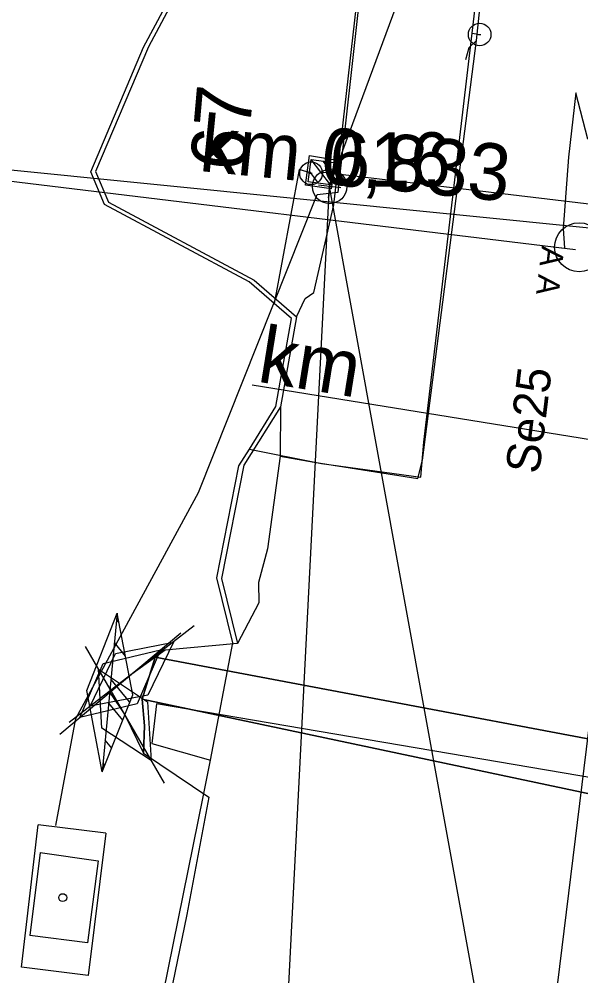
# Model space of a CAD drawing. Extents: x -598638 to -597933, y -1164002 to -1161904.
# Drawn here: x -598553.48 to -598528.63, y -1163497.55 to -1163455.25 of the extents above; entities that cross this region are included whole.
import ezdxf

# ---------------------------------------------------------------- set-up
doc = ezdxf.new("R2010")
doc.units = 0
for name, color, linetype in [('Vrstva 1', 7, 'Continuous'), ('Vrstva 11', 7, 'Continuous'), ('Vrstva 12', 7, 'Continuous'), ('Vrstva 16', 7, 'Continuous'), ('Vrstva 23', 7, 'Continuous'), ('Vrstva 25', 7, 'Continuous'), ('Vrstva 26', 7, 'Continuous'), ('Vrstva 28', 7, 'Continuous'), ('Vrstva 3', 7, 'Continuous'), ('Vrstva 31', 7, 'Continuous'), ('Vrstva 35', 7, 'Continuous'), ('Vrstva 51', 7, 'Continuous'), ('Vrstva 59', 7, 'Continuous'), ('Vrstva 6', 7, 'Continuous'), ('Vrstva 63', 7, 'Continuous'), ('Vrstva 7', 7, 'Continuous')]:
    doc.layers.add(name, color=color, linetype=linetype)

msp = doc.modelspace()

# ---------------------------------------------------------------- linework, layer by layer
at = {"layer": 'Vrstva 1'}
msp.add_line((-598564.645, -1163460.828), (-598504.943, -1163466.8), dxfattribs=at)
at = {"layer": 'Vrstva 11'}
for p, q in [((-598539.706, -1163462.573), (-598540.557, -1163461.449)), ((-598539.631, -1163462.052), (-598540.035, -1163461.518)), ((-598540.231, -1163462.501), (-598540.63, -1163461.974))]:
    msp.add_line(p, q, dxfattribs=at)
msp.add_lwpolyline([(-598540.694, -1163462.437), (-598540.557, -1163461.446), (-598539.566, -1163461.583), (-598539.703, -1163462.574)], close=True, dxfattribs=at)
for points in [[(-598540.694, -1163462.437), (-598540.557, -1163461.446), (-598539.566, -1163461.583), (-598539.703, -1163462.574), (-598540.694, -1163462.437)], [(-598518.75, -1163464.56), (-598540.13, -1163462.01)]]:
    msp.add_lwpolyline(points, dxfattribs=at)
at = {"layer": 'Vrstva 12'}
msp.add_lwpolyline([(-598539.48, -1163461.47), (-598539.67, -1163462.75), (-598540.81, -1163462.58), (-598540.63, -1163461.28), (-598539.48, -1163461.47)], dxfattribs=at)
at = {"layer": 'Vrstva 16'}
for points in [[(-598549.644, -1163491.237), (-598550.426, -1163497.528), (-598553.376, -1163497.172), (-598552.644, -1163490.864)], [(-598549.644, -1163491.237), (-598552.644, -1163490.864)]]:
    msp.add_lwpolyline(points, dxfattribs=at)
at = {"layer": 'Vrstva 23'}
for points in [[(-598552.552, -1163492.091), (-598549.985, -1163492.468), (-598550.449, -1163496.09), (-598553.014, -1163495.766)], [(-598552.552, -1163492.091), (-598553.014, -1163495.766)]]:
    msp.add_lwpolyline(points, dxfattribs=at)
at = {"layer": 'Vrstva 25'}
for p, q in [((-598533.157, -1163455.923), (-598533.057, -1163455.923)), ((-598540.616, -1163462.062), (-598540.516, -1163462.062))]:
    msp.add_line(p, q, dxfattribs=at)
for centre in [(-598533.107, -1163455.923), (-598540.566, -1163462.062)]:
    msp.add_circle(centre, 0.5, dxfattribs=at)
at = {"layer": 'Vrstva 26'}
for points in [[(-598545.332, -1163489.631), (-598545.008, -1163488.013), (-598544.032, -1163482.82), (-598544.736, -1163479.954), (-598543.755, -1163474.998), (-598543.294, -1163474.254), (-598542.12, -1163472.372), (-598541.435, -1163468.483), (-598542.191, -1163467.82), (-598543.3, -1163466.865), (-598549.702, -1163463.438), (-598550.312, -1163461.998), (-598547.972, -1163456.485), (-598545.109, -1163451.121), (-598540.175, -1163430.965), (-598539.287, -1163425.257), (-598536.381, -1163402.898), (-598536.647, -1163397.91), (-598537.412, -1163388.462)], [(-598543.294, -1163474.254), (-598540.098, -1163474.897), (-598535.703, -1163475.505), (-598535.584, -1163473.956), (-598533.441, -1163455.87), (-598532.804, -1163450.473), (-598532.749, -1163449.438), (-598531.188, -1163437.14), (-598531.046, -1163436.005), (-598530.738, -1163436.041)], [(-598551.86, -1163490.896), (-598550.979, -1163486.167), (-598545.539, -1163476.175), (-598540.296, -1163462.996), (-598539.364, -1163462.898), (-598538.397, -1163454.139), (-598537.686, -1163454.273)], [(-598533.441, -1163455.87), (-598533.107, -1163455.923)], [(-598540.566, -1163462.062), (-598541.095, -1163461.89), (-598542.191, -1163467.82)], [(-598515.761, -1163490.906), (-598547.407, -1163485.525), (-598547.611, -1163487.268), (-598545.008, -1163488.013)], [(-598588.761, -1163677.265), (-598581.48, -1163677.548), (-598580.673, -1163676.998), (-598579.793, -1163670.74), (-598579.104, -1163665.83), (-598575.81, -1163633.898), (-598573.543, -1163615.779), (-598569.61, -1163583.767), (-598565.804, -1163555.196), (-598563.346, -1163534.245), (-598552.733, -1163534.833), (-598552.296, -1163533.988), (-598551.287, -1163526.393), (-598548.728, -1163507.111), (-598547.312, -1163499.378), (-598545.332, -1163489.631)]]:
    msp.add_lwpolyline(points, dxfattribs=at)
at = {"layer": 'Vrstva 28'}
for p, q in [((-598545.735, -1163482.079), (-598551.265, -1163486.341)), ((-598546.332, -1163482.39), (-598551.687, -1163486.87)), ((-598550.557, -1163482.987), (-598547.064, -1163489.032)), ((-598549.211, -1163483.288), (-598546.657, -1163482.79)), ((-598546.657, -1163482.79), (-598547.79, -1163485.132)), ((-598550.343, -1163485.63), (-598549.211, -1163483.288)), ((-598549.757, -1163483.737), (-598547.225, -1163483.137)), ((-598547.225, -1163483.137), (-598548.263, -1163485.523)), ((-598550.795, -1163486.123), (-598549.757, -1163483.737)), ((-598549.975, -1163483.995), (-598547.803, -1163485.427)), ((-598549.818, -1163486.592), (-598549.975, -1163483.995)), ((-598547.79, -1163485.132), (-598550.343, -1163485.63)), ((-598548.263, -1163485.523), (-598550.795, -1163486.123)), ((-598547.803, -1163485.427), (-598547.646, -1163488.024)), ((-598547.646, -1163488.024), (-598549.818, -1163486.592))]:
    msp.add_line(p, q, dxfattribs=at)
for points in [[(-598536.213, -1163400.645), (-598536.168, -1163402.882), (-598539.241, -1163426.522), (-598539.962, -1163430.949), (-598541.59, -1163438.158), (-598542.388, -1163441.691), (-598544.896, -1163451.105), (-598547.759, -1163456.469), (-598550.099, -1163461.982), (-598549.524, -1163463.34), (-598543.087, -1163466.786), (-598541.213, -1163468.412), (-598540.83, -1163467.6), (-598540.45, -1163467.34), (-598539.56, -1163463.45), (-598538.42, -1163453.46), (-598538.38, -1163452.75)], [(-598541.213, -1163468.412), (-598541.912, -1163472.382), (-598541.94, -1163474.57), (-598540.43, -1163474.83), (-598535.85, -1163475.55), (-598535.63, -1163474.75), (-598533.25, -1163456.19), (-598532.5, -1163449.06), (-598531.21, -1163437.8), (-598530.49, -1163437.59), (-598530.54, -1163438.36)], [(-598533.25, -1163456.19), (-598533.58, -1163456.51), (-598533.73, -1163457.04)], [(-598514.51, -1163484.35), (-598514.38, -1163480.67), (-598513.13, -1163475.45), (-598512.19, -1163471.82), (-598512.11, -1163471.2), (-598510.35, -1163465.26), (-598510.39, -1163463.95), (-598514.7, -1163462.74), (-598516.79, -1163462.2), (-598518.93, -1163461.77), (-598523.46, -1163461.36), (-598524.57, -1163461.22), (-598525.3, -1163460.94), (-598528.32, -1163460.55), (-598528.85, -1163458.5), (-598529.18, -1163461.35), (-598529.41, -1163464.51), (-598529.36, -1163465.37)], [(-598541.912, -1163472.382), (-598543.54, -1163474.971), (-598544.53, -1163479.976), (-598543.818, -1163482.855)], [(-598541.94, -1163474.57), (-598542.5, -1163478.67), (-598542.89, -1163480.16), (-598542.87, -1163481.06), (-598543.818, -1163482.855), (-598547.027, -1163483.149), (-598548.5, -1163484.21), (-598549.01, -1163484.63), (-598549.47, -1163485.021), (-598548.81, -1163486.01), (-598547.976, -1163487.695), (-598545.092, -1163489.642)], [(-598547.976, -1163487.695), (-598547.93, -1163486.49), (-598548.04, -1163485.31), (-598547.46, -1163483.46), (-598517.45, -1163489.12), (-598516.135, -1163489.246)], [(-598548.04, -1163485.31), (-598518.01, -1163491.67), (-598516.85, -1163491.33)], [(-598545.092, -1163489.642), (-598546.067, -1163494.842), (-598548.252, -1163505.51), (-598549.637, -1163514.935), (-598550.222, -1163519.898), (-598550.57, -1163526.69), (-598552.088, -1163534.212), (-598552.387, -1163534.867), (-598558.986, -1163534.224), (-598563.192, -1163534.27), (-598563.517, -1163536.001), (-598564.063, -1163540.493), (-598564.734, -1163547.322), (-598565.317, -1163553.309), (-598566.354, -1163561.262)]]:
    msp.add_lwpolyline(points, dxfattribs=at)
at = {"layer": 'Vrstva 3'}
msp.add_circle((-598528.707, -1163465.333), 1.084, dxfattribs=at)
at = {"layer": 'Vrstva 31'}
for p, q in [((-598549.065, -1163481.918), (-598549.164, -1163481.801)), ((-598548.768, -1163483.407), (-598549.26, -1163482.814)), ((-598548.597, -1163485.431), (-598549.415, -1163484.441)), ((-598548.893, -1163486.243), (-598549.515, -1163485.491)), ((-598549.376, -1163487.475), (-598549.669, -1163487.121)), ((-598549.704, -1163488.247), (-598549.766, -1163488.134))]:
    msp.add_line(p, q, dxfattribs=at)
for points in [[(-598537.199, -1163388.446), (-598536.213, -1163400.645), (-598536.168, -1163402.882), (-598539.241, -1163426.522), (-598539.962, -1163430.949), (-598541.59, -1163438.158), (-598542.388, -1163441.691), (-598544.896, -1163451.105), (-598547.759, -1163456.469), (-598550.099, -1163461.982), (-598549.524, -1163463.34), (-598543.087, -1163466.786), (-598541.213, -1163468.412), (-598541.912, -1163472.382), (-598543.54, -1163474.971), (-598544.53, -1163479.976), (-598543.818, -1163482.855), (-598547.027, -1163483.149)], [(-598433.21, -1163480.3), (-598433.516, -1163477.441), (-598434.249, -1163476.136), (-598445.277, -1163474.902), (-598453.282, -1163474.057), (-598465.142, -1163473.014), (-598476.47, -1163471.867), (-598477.633, -1163472.175), (-598478.209, -1163473.453), (-598480.422, -1163481.099), (-598481.698, -1163484.769), (-598483.15, -1163485.678), (-598488.83, -1163486.39), (-598490.871, -1163486.311), (-598512.372, -1163485.579), (-598514.383, -1163486.119), (-598515.446, -1163487.289), (-598516.135, -1163489.246), (-598517.45, -1163489.12), (-598547.46, -1163483.46), (-598548.04, -1163485.31), (-598547.93, -1163486.49), (-598547.976, -1163487.695)], [(-598549.803, -1163488.529), (-598550.483, -1163484.925), (-598549.137, -1163481.513)], [(-598547.027, -1163483.149), (-598548.5, -1163484.21), (-598549.01, -1163484.63), (-598549.47, -1163485.021), (-598548.81, -1163486.01), (-598547.976, -1163487.695)], [(-598547.976, -1163487.695), (-598545.092, -1163489.642), (-598546.067, -1163494.842), (-598548.252, -1163505.51), (-598549.637, -1163514.935), (-598550.222, -1163519.898), (-598550.57, -1163526.69), (-598552.088, -1163534.212), (-598552.387, -1163534.867), (-598558.986, -1163534.224), (-598563.192, -1163534.27), (-598563.517, -1163536.001), (-598564.063, -1163540.493), (-598564.734, -1163547.322), (-598565.317, -1163553.309), (-598566.354, -1163561.262)]]:
    msp.add_lwpolyline(points, dxfattribs=at)
msp.add_lwpolyline([(-598549.803, -1163488.529), (-598548.457, -1163485.117), (-598549.137, -1163481.513)], close=True, dxfattribs=at)
at = {"layer": 'Vrstva 35'}
for points in [[(-598549.524, -1163463.34), (-598543.087, -1163466.786), (-598541.213, -1163468.412)], [(-598517.45, -1163489.12), (-598547.46, -1163483.46)], [(-598518.01, -1163491.67), (-598548.04, -1163485.31)]]:
    msp.add_lwpolyline(points, dxfattribs=at)
at = {"layer": 'Vrstva 51'}
msp.add_lwpolyline([(-598538.768, -1163586.309), (-598539.802, -1163586.224), (-598538.809, -1163572.569), (-598537.239, -1163559.929), (-598532.111, -1163517.921), (-598526.717, -1163473.944), (-598521.465, -1163429.602), (-598514.887, -1163376.546), (-598510.204, -1163338.254)], dxfattribs=at)
at = {"layer": 'Vrstva 59'}
msp.add_circle((-598551.549, -1163494.09), 0.175, dxfattribs=at)
at = {"layer": 'Vrstva 6'}
for p, q in [((-598569.071, -1163460.563), (-598529.36, -1163465.37)), ((-598529.857, -1163465.31), (-598528.864, -1163465.431)), ((-598543.17, -1163471.421), (-598503.68, -1163477.79))]:
    msp.add_line(p, q, dxfattribs=at)
at = {"layer": 'Vrstva 63'}
for p, q in [((-598539.744, -1163462.649), (-598508.824, -1163378.896)), ((-598554.868, -1163759.055), (-598539.744, -1163462.649)), ((-598539.794, -1163462.649), (-598539.694, -1163462.649)), ((-598520.489, -1163568.592), (-598539.744, -1163462.649))]:
    msp.add_line(p, q, dxfattribs=at)
msp.add_circle((-598539.744, -1163462.649), 0.756, dxfattribs=at)
at = {"layer": 'Vrstva 7'}
for p, q in [((-598539.683, -1163462.153), (-598539.805, -1163463.145)), ((-598539.248, -1163462.71), (-598540.24, -1163462.588))]:
    msp.add_line(p, q, dxfattribs=at)

# ---------------------------------------------------------------- texts
at = {"layer": 'Vrstva 1'}
msp.add_text('km 0,833', height=2.5, rotation=354.3127, dxfattribs=at).set_placement((-598545.562, -1163461.955))
at = {"layer": 'Vrstva 11'}
msp.add_text('67', height=2.5, rotation=84.9676, dxfattribs=at).set_placement((-598543.435, -1163462.01))
at = {"layer": 'Vrstva 6'}
for s, height, rotation, p in [('A A', 1, 263.097, (-598530.353, -1163465.25)), ('km ', 2.5, 350.8382, (-598542.996, -1163471.268)), ('Se25', 1.5, 83.097, (-598530.476, -1163475.388))]:
    msp.add_text(s, height=height, rotation=rotation, dxfattribs=at).set_placement(p)
at = {"layer": 'Vrstva 63'}
msp.add_text('616', height=2.4, dxfattribs=at).set_placement((-598539.744, -1163462.649))

doc.saveas('drawing.dxf')
